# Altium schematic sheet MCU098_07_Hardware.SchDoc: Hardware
size 431 x 279 mm; Date: Not shown in title block; ApprovedBy: Not shown in title block; CheckedBy: Not shown in title block; Author: Not shown in title block; CompanyName: Not shown in title block; DrawnBy: Johnson He; Engineer: Not shown in title block; Organization: Not shown in title block; Address1: Not shown in title block; Address2: Not shown in title block; Address3: Not shown in title block; Address4: Not shown in title block; DocumentNumber: 1; Revision: Use project parameter SCH_Rev; SheetNumber: 7; SheetTotal: 7; PageSetup: Record=PageOptions¦CenterHorizontal=True¦CenterVertical=True¦PrintScale=1.00¦XCorrection=1.00¦YCorrection=1.00¦PrintKind=0¦BorderSize=5000000¦LeftOffset=0¦BottomOffset=0¦Orientation=2¦PaperLength=1000¦PaperWidth=1000¦Scale=100¦PaperSource=15¦PrintQuality=600¦MediaType=1¦DitherType=10¦PaperKind=Letter¦PrintScaleMode=1
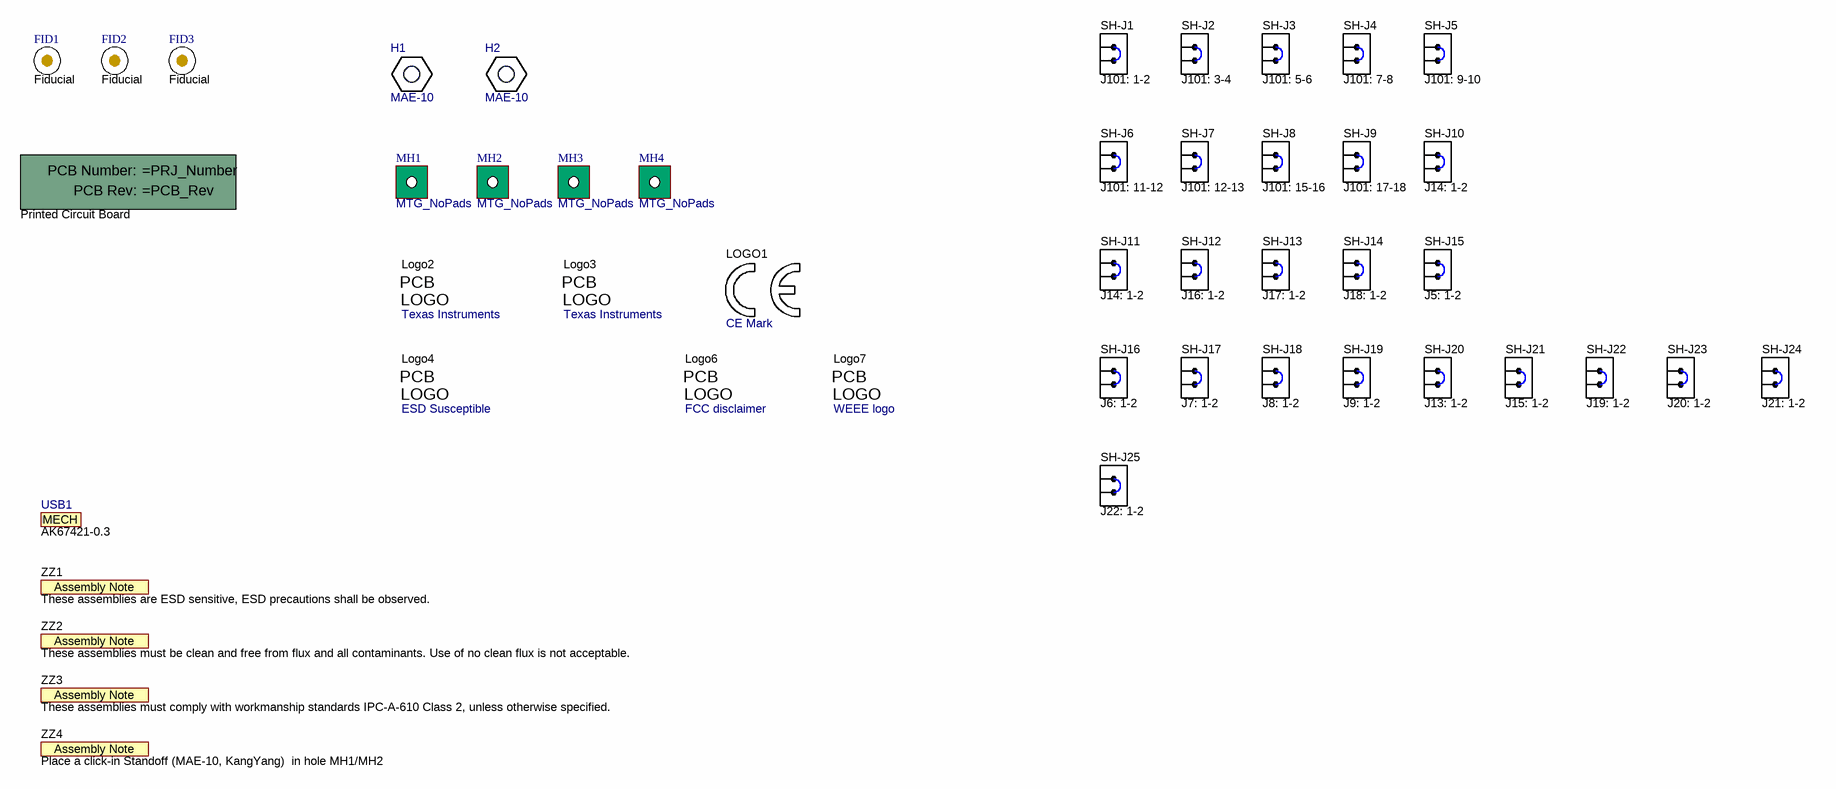
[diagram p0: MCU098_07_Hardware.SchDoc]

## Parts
!PCB1  Printed Circuit Board  (mechanical)
FID1  Fiducial  [Fiducial10-30]
FID2  Fiducial  [Fiducial10-30]
FID3  Fiducial  [Fiducial10-30]
H1  MAE-10  [KY_MAE-10]
H2  MAE-10  [KY_MAE-10]
LOGO1  CE Mark  [CE_Mark_5mm]  (no BOM)
Logo2  Texas Instruments  [TI_Horizontal_Overlay_Small]  (no BOM)
Logo3  Texas Instruments  [TI_Horizontal_Overlay_Medium]  (no BOM)
Logo4  ESD Susceptible  [ESD_Overlay_Large]  (no BOM)
Logo6  FCC disclaimer  [FCC_disclaimer]  (no BOM)
Logo7  WEEE logo  [WEEE_Minimum]  (no BOM)
MH1  MTG_NoPads  [NPTH125mil]  (no BOM)
MH2  MTG_NoPads  [NPTH125mil]  (no BOM)
MH3  MTG_NoPads  [NPTH125mil]  (no BOM)
MH4  MTG_NoPads  [NPTH125mil]  (no BOM)
SH-J1  value J101: 1-2  [SNT-100-BK-G]  (hidden comment: SNT-100-BK-G)
SH-J2  value J101: 3-4  [SNT-100-BK-G]  (hidden comment: SNT-100-BK-G)
SH-J3  value J101: 5-6  [SNT-100-BK-G]  (hidden comment: SNT-100-BK-G)
SH-J4  value J101: 7-8  [SNT-100-BK-G]  (hidden comment: SNT-100-BK-G)
SH-J5  value J101: 9-10  [SNT-100-BK-G]  (hidden comment: SNT-100-BK-G)
SH-J6  value J101: 11-12  [SNT-100-BK-G]  (hidden comment: SNT-100-BK-G)
SH-J7  value J101: 12-13  [SNT-100-BK-G]  (hidden comment: SNT-100-BK-G)
SH-J8  value J101: 15-16  [SNT-100-BK-G]  (hidden comment: SNT-100-BK-G)
SH-J9  value J101: 17-18  [SNT-100-BK-G]  (hidden comment: SNT-100-BK-G)
SH-J10  value J14: 1-2  [SNT-100-BK-G]  (hidden comment: SNT-100-BK-G)
SH-J11  value J14: 1-2  [SNT-100-BK-G]  (hidden comment: SNT-100-BK-G)
SH-J12  value J16: 1-2  [SNT-100-BK-G]  (hidden comment: SNT-100-BK-G)
SH-J13  value J17: 1-2  [SNT-100-BK-G]  (hidden comment: SNT-100-BK-G)
SH-J14  value J18: 1-2  [SNT-100-BK-G]  (hidden comment: SNT-100-BK-G)
SH-J15  value J5: 1-2  [SNT-100-BK-G]  (hidden comment: SNT-100-BK-G)
SH-J16  value J6: 1-2  [SNT-100-BK-G]  (hidden comment: SNT-100-BK-G)
SH-J17  value J7: 1-2  [SNT-100-BK-G]  (hidden comment: SNT-100-BK-G)
SH-J18  value J8: 1-2  [SNT-100-BK-G]  (hidden comment: SNT-100-BK-G)
SH-J19  value J9: 1-2  [SNT-100-BK-G]  (hidden comment: SNT-100-BK-G)
SH-J20  value J13: 1-2  [SNT-100-BK-G]  (hidden comment: SNT-100-BK-G)
SH-J21  value J15: 1-2  [SNT-100-BK-G]  (hidden comment: SNT-100-BK-G)
SH-J22  value J19: 1-2  [SNT-100-BK-G]  (hidden comment: SNT-100-BK-G)
SH-J23  value J20: 1-2  [SNT-100-BK-G]  (hidden comment: SNT-100-BK-G)
SH-J24  value J21: 1-2  [SNT-100-BK-G]  (hidden comment: SNT-100-BK-G)
SH-J25  value J22: 1-2  [SNT-100-BK-G]  (hidden comment: SNT-100-BK-G)
USB1  AK67421-0.3  (mechanical)
ZZ1  These assemblies are ESD sensitive, ESD precautions shall be observed.  [AssemblyNote]  (no BOM)
ZZ2  These assemblies must be clean and free from flux and all contaminants. Use of no clean flux is not acceptable.  [AssemblyNote]  (no BOM)
ZZ3  These assemblies must comply with workmanship standards IPC-A-610 Class 2, unless otherwise specified.  [AssemblyNote]  (no BOM)
ZZ4  Place a click-in Standoff (MAE-10, KangYang)  in hole MH1/MH2  [AssemblyNote]  (no BOM)

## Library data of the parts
!PCB1 = CMP-0003618-2: Manufacturer: Any
FID1-FID3 = CMP-0077181-1: Fiducial mark.  There is nothing to buy or mount.
H1 H2 = CMP-0077978-1: Spacer Support, Nylon 66; Manufacturer: Kang Yang; CompType: Standoff
LOGO1 = CMP-0074844-1: SymbolCreator: a0412235
Logo2 Logo3 = CMP-0074838-1: Texas Instrument Corporate Signature; SymbolCreator: a0412235; Lib Reference: TI_Logo
Logo4 = CMP-0074840-1: ESD Susceptible Symbol; SymbolCreator: a0412235; Lib Reference: ESD_Susceptible
Logo6 = CMP-0074847-1: FCC_disclaimer
Logo7 = CMP-0074769-1
MH1-MH4 = CMP-0078424-2: PCB Mounting Hole, No Pad; Manufacturer: Any; Key: Mounting Hole (non-standard) No Pad
SH-J1-SH-J25 = CMP-0003623-3: Shunt, 100mil, Gold plated, Black; Alternate PartNumber: 969102-0000-DA; Manufacturer: Samtec; Alternate Manufacturer: 3M
USB1 = CMP-0077983-1: Cable, USB-A to micro USB-B, 0.3 m; Manufacturer: Assman WSW
ZZ1-ZZ4 = AssemblyNote: SymbolCreator: codlsc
